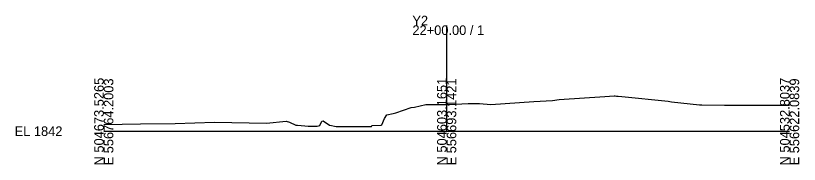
# Model space of a CAD drawing. Extents: x -26 to 203, y -10 to 3574.
# Drawn here: x -25.7 to 202.8, y 1990.3 to 2033.8 of the extents above; entities that cross this region are included whole.
import ezdxf

# ---------------------------------------------------------------- set-up
doc = ezdxf.new("R2010")
doc.units = 0
doc.layers.add('Exist Cross Section Cell', color=7, linetype='Continuous')
doc.layers.add('Exist XS Ground Line', color=7, linetype='Continuous')

msp = doc.modelspace()

# ---------------------------------------------------------------- linework, layer by layer
at = {"layer": 'Exist Cross Section Cell'}
for p, q in [((100, 2000), (100, 2030.91)), ((0, 2000), (100, 2000)), ((100, 2000), (200, 2000))]:
    msp.add_line(p, q, dxfattribs=at)
at = {"layer": 'Exist XS Ground Line'}
for p, q in [((125.43, 2008.67), (130.86, 2009)), ((130.86, 2009), (132.81, 2009.21)), ((132.81, 2009.21), (146.14, 2010.16)), ((146.14, 2010.16), (148.81, 2010.3)), ((148.81, 2010.3), (149.16, 2010.28)), ((149.16, 2010.28), (149.52, 2010.26)), ((149.52, 2010.26), (150.01, 2010.22)), ((150.01, 2010.22), (151.12, 2010.13)), ((151.12, 2010.13), (164.56, 2008.81)), ((164.56, 2008.81), (165.61, 2008.59)), ((85.14, 2005.35), (89.62, 2006.88)), ((89.62, 2006.88), (90.57, 2006.99)), ((90.57, 2006.99), (93.95, 2007.76)), ((93.95, 2007.76), (100, 2007.79)), ((100, 2007.79), (100.78, 2007.79)), ((100.78, 2007.79), (106.22, 2008.06)), ((106.22, 2008.06), (109.53, 2008.05)), ((109.53, 2008.05), (112.92, 2007.75)), ((112.92, 2007.75), (125.43, 2008.67)), ((165.61, 2008.59), (173.74, 2007.73)), ((173.74, 2007.73), (174.36, 2007.73)), ((174.36, 2007.73), (181.04, 2007.62)), ((181.04, 2007.62), (183.41, 2007.63)), ((183.41, 2007.63), (199.66, 2007.62)), ((199.66, 2007.62), (200, 2007.62)), ((81.85, 2003.67), (82.52, 2004.79)), ((82.52, 2004.79), (84.36, 2005.12)), ((84.36, 2005.12), (85.14, 2005.35)), ((0, 2001.97), (10.7, 2002.19)), ((10.7, 2002.19), (20.85, 2002.28)), ((20.85, 2002.28), (32.27, 2002.65)), ((32.27, 2002.65), (47.48, 2002.3)), ((47.48, 2002.3), (53.19, 2002.89)), ((53.19, 2002.89), (54.15, 2002.67)), ((54.15, 2002.67), (56.05, 2001.73)), ((62.99, 2001.69), (63.6, 2002.97)), ((63.6, 2002.97), (63.99, 2003.06)), ((63.99, 2003.06), (65.84, 2001.78)), ((81.08, 2001.86), (81.85, 2003.67)), ((56.05, 2001.73), (56.47, 2001.72)), ((56.47, 2001.72), (58.6, 2001.57)), ((58.6, 2001.57), (59.65, 2001.44)), ((59.65, 2001.44), (60.09, 2001.45)), ((60.09, 2001.45), (61.28, 2001.46)), ((61.28, 2001.46), (62.27, 2001.51)), ((62.27, 2001.51), (62.99, 2001.69)), ((65.84, 2001.78), (65.89, 2001.79)), ((65.89, 2001.79), (67.75, 2001.4)), ((67.75, 2001.4), (78.11, 2001.36)), ((78.11, 2001.36), (78.15, 2001.63)), ((78.15, 2001.63), (80.92, 2001.73)), ((80.92, 2001.73), (81.08, 2001.86))]:
    msp.add_line(p, q, dxfattribs=at)

# ---------------------------------------------------------------- texts
at = {"layer": 'Exist Cross Section Cell'}
for s, p in [('Y2', (90, 2030.91)), ('22+00.00 / 1', (90, 2028.11)), ('EL 1842', (-26, 1998.6))]:
    msp.add_text(s, height=2.8, dxfattribs=at).set_placement(p)
for s, p in [('N 504673.5265', (0, 1990)), ('E 556764.2003', (2.8, 1990)), ('N 504603.1651', (100, 1990)), ('E 556693.1421', (102.8, 1990)), ('N 504532.8037', (200, 1990)), ('E 556622.0839', (202.8, 1990))]:
    msp.add_text(s, height=2.8, rotation=90, dxfattribs=at).set_placement(p)

doc.saveas('drawing.dxf')
